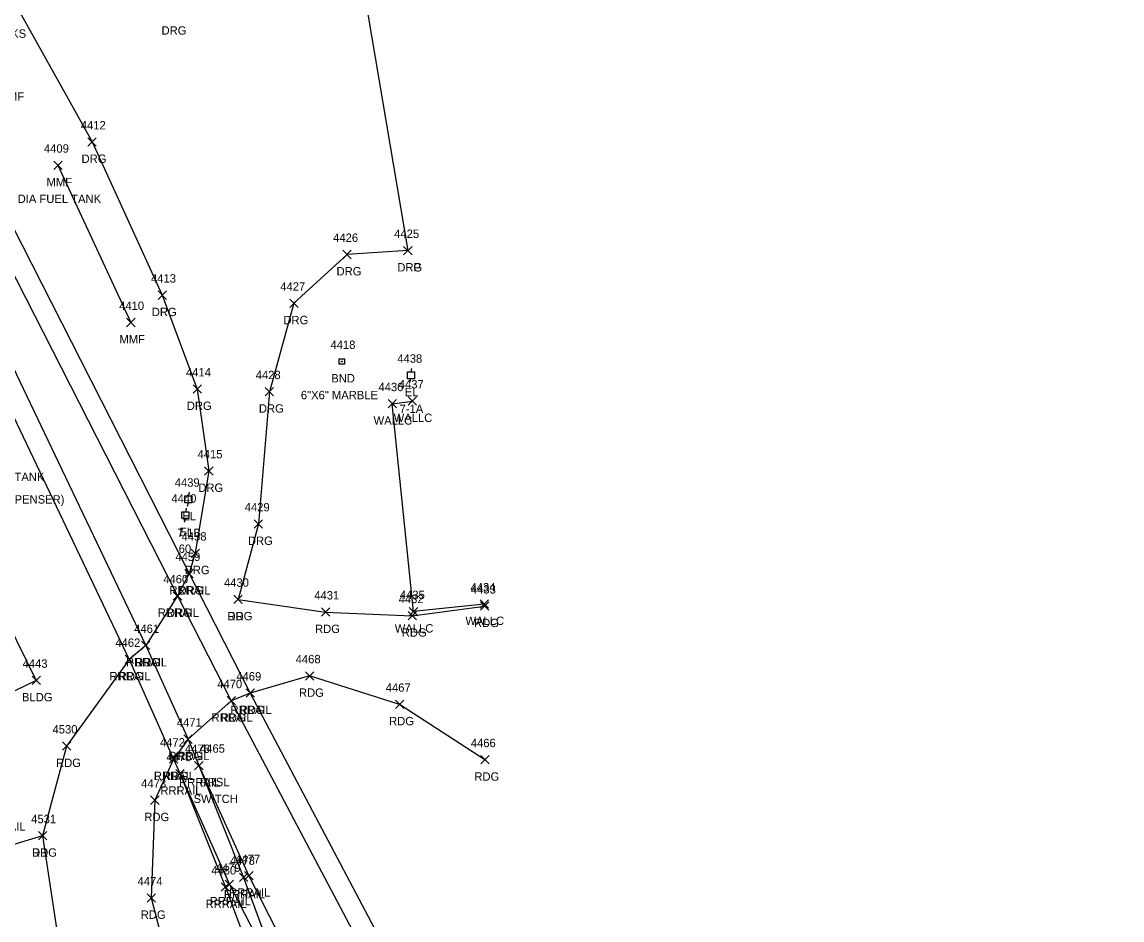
# Model space of a CAD drawing. Extents: x 1462668 to 1465147, y 550359 to 557351.
# Drawn here: x 1463947.5 to 1464209.9, y 555056.5 to 555270.7 of the extents above; entities that cross this region are included whole.
import ezdxf

# ---------------------------------------------------------------- set-up
doc = ezdxf.new("R2010")
doc.units = 0
for name, color, linetype in [('L_A', 7, 'Continuous'), ('L_C', 7, 'Continuous'), ('L_I', 7, 'Continuous'), ('L_TIC', 7, 'Continuous'), ('LBC', 7, 'Continuous'), ('LDEFAULT', 7, 'Continuous'), ('Level 18', 7, 'Continuous'), ('LW', 7, 'Continuous'), ('M_A', 7, 'Continuous'), ('M_C', 7, 'Continuous'), ('M_I', 7, 'Continuous'), ('P_A', 7, 'Continuous'), ('P_I', 7, 'Continuous'), ('P_TIC', 7, 'Continuous'), ('PEU', 7, 'Continuous'), ('R_A', 7, 'Continuous'), ('R_C', 7, 'Continuous'), ('R_I', 7, 'Continuous'), ('R_TIC', 7, 'Continuous'), ('RDG', 7, 'Continuous'), ('RDP', 7, 'Continuous'), ('RR', 7, 'Continuous'), ('U_A', 7, 'Continuous'), ('U_C', 7, 'Continuous'), ('U_I', 7, 'Continuous'), ('UEPT', 7, 'Continuous')]:
    doc.layers.add(name, color=color, linetype=linetype)

msp = doc.modelspace()

# ---------------------------------------------------------------- linework, layer by layer
at = {"layer": 'L_TIC'}
for points in [[(1463955.08, 555235.52), (1463957.08, 555237.52)], [(1463957.08, 555235.52), (1463955.08, 555237.52)], [(1463972.47, 555198.01), (1463974.47, 555200.01)], [(1463974.47, 555198.01), (1463972.47, 555200.01)], [(1464034.86, 555178.64), (1464036.86, 555180.64)], [(1464036.86, 555178.64), (1464034.86, 555180.64)], [(1464039.65, 555179.29), (1464041.65, 555181.29)], [(1464041.65, 555179.29), (1464039.65, 555181.29)], [(1464056.78, 555130.87), (1464058.78, 555132.87)], [(1464058.78, 555130.87), (1464056.78, 555132.87)], [(1464039.91, 555129.06), (1464041.91, 555131.06)], [(1464041.91, 555129.06), (1464039.91, 555131.06)], [(1463949.91, 555112.66), (1463951.91, 555114.66)], [(1463951.91, 555112.66), (1463949.91, 555114.66)]]:
    msp.add_lwpolyline(points, dxfattribs=at)
at = {"layer": 'LBC'}
msp.add_lwpolyline([(1463936.65, 555142.43), (1463950.91, 555113.66), (1463943.32, 555109.94), (1463929.12, 555138.49)], dxfattribs=at)
at = {"layer": 'LDEFAULT'}
msp.add_lwpolyline([(1463956.08, 555236.52), (1463973.47, 555199.01)], dxfattribs=at)
at = {"layer": 'Level 18'}
msp.add_lwpolyline([(1464023.17, 555190.33), (1464024.42, 555190.33), (1464024.42, 555189.08), (1464023.17, 555189.08)], close=True, dxfattribs=at)
msp.add_circle((1464023.8, 555189.71), 0.0833, dxfattribs=at)
at = {"layer": 'LW'}
msp.add_lwpolyline([(1464057.78, 555131.87), (1464040.91, 555130.06), (1464035.86, 555179.64), (1464040.65, 555180.29)], dxfattribs=at)
at = {"layer": 'P_TIC'}
for points in [[(1463998.05, 555131.98), (1464000.05, 555133.98)], [(1464000.05, 555131.98), (1463998.05, 555133.98)], [(1464018.93, 555128.95), (1464020.93, 555130.95)], [(1464020.93, 555128.95), (1464018.93, 555130.95)], [(1464039.63, 555128.08), (1464041.63, 555130.08)], [(1464041.63, 555128.08), (1464039.63, 555130.08)], [(1464056.86, 555130.37), (1464058.86, 555132.37)], [(1464058.86, 555130.37), (1464056.86, 555132.37)], [(1463976.02, 555120.98), (1463978.02, 555122.98)], [(1463978.02, 555120.98), (1463976.02, 555122.98)], [(1463972.09, 555117.65), (1463974.09, 555119.65)], [(1463974.09, 555117.65), (1463972.09, 555119.65)], [(1464015.11, 555113.73), (1464017.11, 555115.73)], [(1464017.11, 555113.73), (1464015.11, 555115.73)], [(1464000.96, 555109.62), (1464002.96, 555111.62)], [(1464002.96, 555109.62), (1464000.96, 555111.62)], [(1463996.43, 555107.79), (1463998.43, 555109.79)], [(1463998.43, 555107.79), (1463996.43, 555109.79)], [(1464036.6, 555106.94), (1464038.6, 555108.94)], [(1464038.6, 555106.94), (1464036.6, 555108.94)], [(1463957.14, 555096.99), (1463959.14, 555098.99)], [(1463959.14, 555096.99), (1463957.14, 555098.99)], [(1463986.14, 555098.63), (1463988.14, 555100.63)], [(1463988.14, 555098.63), (1463986.14, 555100.63)], [(1463982.69, 555093.87), (1463984.69, 555095.87)], [(1463984.69, 555093.87), (1463982.69, 555095.87)], [(1464056.94, 555093.72), (1464058.94, 555095.72)], [(1464058.94, 555093.72), (1464056.94, 555095.72)], [(1463978.2, 555084.08), (1463980.2, 555086.08)], [(1463980.2, 555084.08), (1463978.2, 555086.08)], [(1463951.41, 555075.59), (1463953.41, 555077.59)], [(1463953.41, 555075.59), (1463951.41, 555077.59)], [(1463977.35, 555060.77), (1463979.35, 555062.77)], [(1463979.35, 555060.77), (1463977.35, 555062.77)]]:
    msp.add_lwpolyline(points, dxfattribs=at)
at = {"layer": 'PEU'}
for points in [[(1463999.05, 555132.98), (1464019.93, 555129.95), (1464040.63, 555129.08), (1464057.86, 555131.37)], [(1463977.02, 555121.98), (1463973.09, 555118.65), (1463958.14, 555097.99), (1463952.41, 555076.59), (1463958.37, 555037.25), (1463974.3, 554985.88), (1463991.77, 554931.62), (1464003.96, 554890.94), (1464011.44, 554869.69), (1464014.63, 554855.08), (1464021.09, 554834.4), (1464036.69, 554798.98), (1464052.01, 554759.21), (1464073.2, 554710.63), (1464082.37, 554701.78), (1464089.9, 554691.06)], [(1464057.94, 555094.72), (1464037.6, 555107.94), (1464016.11, 555114.73), (1464001.96, 555110.62), (1463997.43, 555108.79), (1463987.14, 555099.63), (1463983.69, 555094.87), (1463979.2, 555085.08), (1463978.35, 555061.77), (1463988.09, 555023.99)]]:
    msp.add_lwpolyline(points, dxfattribs=at)
at = {"layer": 'R_TIC'}
for points in [[(1463963.23, 555241.07), (1463965.23, 555243.07)], [(1463965.23, 555241.07), (1463963.23, 555243.07)], [(1464038.56, 555215.18), (1464040.56, 555217.18)], [(1464040.56, 555215.18), (1464038.56, 555217.18)], [(1464038.56, 555215.18), (1464040.56, 555217.18)], [(1464040.56, 555215.18), (1464038.56, 555217.18)], [(1464024.06, 555214.24), (1464026.06, 555216.24)], [(1464026.06, 555214.24), (1464024.06, 555216.24)], [(1463979.98, 555204.53), (1463981.98, 555206.53)], [(1463981.98, 555204.53), (1463979.98, 555206.53)], [(1464011.38, 555202.6), (1464013.38, 555204.6)], [(1464013.38, 555202.6), (1464011.38, 555204.6)], [(1463988.33, 555182.15), (1463990.33, 555184.15)], [(1463990.33, 555182.15), (1463988.33, 555184.15)], [(1464005.53, 555181.51), (1464007.53, 555183.51)], [(1464007.53, 555181.51), (1464005.53, 555183.51)], [(1463991.08, 555162.61), (1463993.08, 555164.61)], [(1463993.08, 555162.61), (1463991.08, 555164.61)], [(1464002.92, 555149.96), (1464004.92, 555151.96)], [(1464004.92, 555149.96), (1464002.92, 555151.96)], [(1463987.84, 555142.99), (1463989.84, 555144.99)], [(1463989.84, 555142.99), (1463987.84, 555144.99)], [(1463986.38, 555138.13), (1463988.38, 555140.13)], [(1463988.38, 555138.13), (1463986.38, 555140.13)], [(1463986.38, 555138.13), (1463988.38, 555140.13)], [(1463988.38, 555138.13), (1463986.38, 555140.13)], [(1463983.61, 555132.81), (1463985.61, 555134.81)], [(1463985.61, 555132.81), (1463983.61, 555134.81)], [(1463983.61, 555132.81), (1463985.61, 555134.81)], [(1463985.61, 555132.81), (1463983.61, 555134.81)], [(1463998.05, 555131.98), (1464000.05, 555133.98)], [(1464000.05, 555131.98), (1463998.05, 555133.98)], [(1463976.02, 555120.98), (1463978.02, 555122.98)], [(1463978.02, 555120.98), (1463976.02, 555122.98)], [(1463976.02, 555120.98), (1463978.02, 555122.98)], [(1463978.02, 555120.98), (1463976.02, 555122.98)], [(1463972.09, 555117.65), (1463974.09, 555119.65)], [(1463974.09, 555117.65), (1463972.09, 555119.65)], [(1464000.96, 555109.62), (1464002.96, 555111.62)], [(1464002.96, 555109.62), (1464000.96, 555111.62)], [(1463996.43, 555107.79), (1463998.43, 555109.79)], [(1463998.43, 555107.79), (1463996.43, 555109.79)], [(1463986.14, 555098.63), (1463988.14, 555100.63)], [(1463988.14, 555098.63), (1463986.14, 555100.63)], [(1463982.69, 555093.87), (1463984.69, 555095.87)], [(1463984.69, 555093.87), (1463982.69, 555095.87)], [(1463988.7, 555092.34), (1463990.7, 555094.34)], [(1463990.7, 555092.34), (1463988.7, 555094.34)], [(1463988.7, 555092.34), (1463990.7, 555094.34)], [(1463990.7, 555092.34), (1463988.7, 555094.34)], [(1463984.23, 555090.39), (1463986.23, 555092.39)], [(1463986.23, 555090.39), (1463984.23, 555092.39)], [(1463984.23, 555090.39), (1463986.23, 555092.39)], [(1463986.23, 555090.39), (1463984.23, 555092.39)], [(1463951.41, 555075.59), (1463953.41, 555077.59)], [(1463953.41, 555075.59), (1463951.41, 555077.59)], [(1463999.39, 555065.67), (1464001.39, 555067.67)], [(1464001.39, 555065.67), (1463999.39, 555067.67)], [(1464000.63, 555066.05), (1464002.63, 555068.05)], [(1464002.63, 555066.05), (1464000.63, 555068.05)], [(1463995.02, 555063.35), (1463997.02, 555065.35)], [(1463997.02, 555063.35), (1463995.02, 555065.35)], [(1463996, 555064), (1463998, 555066)], [(1463998, 555064), (1463996, 555066)]]:
    msp.add_lwpolyline(points, dxfattribs=at)
at = {"layer": 'RDG'}
for points in [[(1463767.62, 555582.4), (1463756, 555576.04), (1463782.39, 555530.05), (1463811.87, 555483.03), (1463842.18, 555423.16), (1463871.29, 555375.01), (1463902.25, 555330.66), (1463943.27, 555279.83), (1463964.23, 555242.07), (1463980.98, 555205.53), (1463989.33, 555183.15), (1463992.08, 555163.61), (1463988.84, 555143.99), (1463987.38, 555139.13), (1463984.61, 555133.81), (1463977.02, 555121.98)], [(1464039.56, 555216.18), (1464025.06, 555215.24), (1464012.38, 555203.6), (1464006.53, 555182.51), (1464003.92, 555150.96), (1463999.05, 555132.98)], [(1463952.41, 555076.59), (1463933.98, 555071.02), (1463919.59, 555078.27), (1463901.44, 555117.76), (1463887.25, 555155.23), (1463873.79, 555184.26), (1463863.04, 555181.69)]]:
    msp.add_lwpolyline(points, dxfattribs=at)
at = {"layer": 'RDP'}
msp.add_lwpolyline([(1464023.21, 555313.06), (1464039.56, 555216.18)], dxfattribs=at)
at = {"layer": 'RR'}
for points in [[(1463738.3, 555592.1), (1463756.39, 555555.83), (1463773.18, 555522.79), (1463783.39, 555502.23), (1463795.59, 555478.87), (1463816.57, 555437.48), (1463830.94, 555409.51), (1463848.79, 555374.55), (1463899.55, 555272.92), (1463973.09, 555118.65), (1463983.69, 555094.87), (1463985.23, 555091.39), (1463997, 555065), (1464011.61, 555036.65), (1464026.5, 555008.18), (1464046.45, 554964.72), (1464065.66, 554916.67), (1464082.8, 554871.21), (1464093.87, 554842.43), (1464100.4, 554825.05), (1464129.92, 554747.44), (1464153.38, 554685.33), (1464180.48, 554613.64)], [(1463742.84, 555594.32), (1463760.75, 555558.08), (1463777.72, 555524.42), (1463787.9, 555504.12), (1463799.93, 555481.15), (1463819.96, 555441.9), (1463835.07, 555412.08), (1463853.2, 555376.47), (1463903.47, 555275.99), (1463977.02, 555121.98), (1463987.14, 555099.63), (1463989.7, 555093.34), (1464001.63, 555067.05), (1464016.17, 555038.45), (1464031.3, 555009.85), (1464051, 554966.45), (1464070.2, 554918.71), (1464087.5, 554872.76), (1464098.32, 554844.67), (1464105, 554826.89), (1464134.6, 554748.85), (1464158.08, 554686.95), (1464184.75, 554615.39)], [(1463799.93, 555481.15), (1463821.59, 555442.67), (1463839.41, 555414.19), (1463860.65, 555380.51), (1463909.95, 555291.33), (1463987.38, 555139.13), (1464001.96, 555110.62), (1464033.86, 555050.25), (1464055.66, 555009.67), (1464073.58, 554976.54), (1464098.59, 554931.9), (1464124.97, 554884.13), (1464136.72, 554860.51), (1464143.75, 554841.03), (1464169.78, 554757.06), (1464181.89, 554716.52), (1464214.17, 554610.47)], [(1463795.59, 555478.87), (1463818.35, 555438.44), (1463835.07, 555412.08), (1463856.18, 555378.13), (1463905.6, 555288.89), (1463984.61, 555133.81), (1463997.43, 555108.79), (1464030.1, 555046.89), (1464051.29, 555007.39), (1464069.23, 554974.41), (1464094.51, 554929.11), (1464121.14, 554880.83), (1464131.94, 554858.78), (1464139.09, 554839.52), (1464165.13, 554755.41), (1464177.59, 554713.72), (1464209.39, 554609.15)], [(1463989.7, 555093.34), (1464000.39, 555066.67), (1464022.62, 555006.41), (1464038.48, 554961.39), (1464055.17, 554912.23), (1464070.15, 554864.86), (1464079, 554837.21), (1464085.94, 554816.06), (1464092.4, 554795.76), (1464104.92, 554760.13), (1464114.82, 554731.8), (1464136.23, 554672.67), (1464181.12, 554559.09)], [(1463985.23, 555091.39), (1463996.02, 555064.35), (1464007.14, 555034.52), (1464018.03, 555004.65), (1464033.98, 554959.37), (1464050.76, 554909.64), (1464065.33, 554863.33), (1464074.3, 554835.57), (1464081.74, 554812.78), (1464087.8, 554794.52), (1464102.09, 554753.11), (1464110.14, 554729.95), (1464132.08, 554670.21), (1464176.36, 554557.09)]]:
    msp.add_lwpolyline(points, dxfattribs=at)
at = {"layer": 'UEPT'}
for p, q in [((1464040.46, 555188.08), (1464040.3, 555187.25)), ((1464039.46, 555185.58), (1464039.46, 555187.25)), ((1464039.46, 555187.25), (1464041.13, 555187.25)), ((1464041.13, 555185.58), (1464039.46, 555185.58)), ((1464040.05, 555184.75), (1464040.3, 555185.58)), ((1464040.3, 555186.42), (1464040.3, 555186.42)), ((1464041.13, 555187.25), (1464041.13, 555185.58)), ((1463986.38, 555156.02), (1463986.38, 555157.68)), ((1463986.38, 555157.68), (1463988.05, 555157.68)), ((1463987.38, 555158.52), (1463987.21, 555157.68)), ((1463987.21, 555156.85), (1463987.21, 555156.85)), ((1463988.05, 555157.68), (1463988.05, 555156.02)), ((1463985.67, 555152.23), (1463985.67, 555153.89)), ((1463985.67, 555153.89), (1463987.34, 555153.89)), ((1463988.05, 555156.02), (1463986.38, 555156.02)), ((1463986.67, 555154.73), (1463986.5, 555153.89)), ((1463986.96, 555155.18), (1463987.21, 555156.02)), ((1463987.34, 555153.89), (1463987.34, 555152.23)), ((1463987.34, 555152.23), (1463985.67, 555152.23)), ((1463986.25, 555151.39), (1463986.5, 555152.23)), ((1463986.5, 555153.06), (1463986.5, 555153.06))]:
    msp.add_line(p, q, dxfattribs=at)

# ---------------------------------------------------------------- texts
at = {"layer": 'L_A'}
for s, p in [('MMF', (1463941.92, 555251.92)), ('MMF', (1463953.37, 555231.52)), ('MMF', (1463970.75, 555194.01)), ('WALLC', (1464036.18, 555175.29)), ('WALLC', (1464031.39, 555174.64)), ('WALLC', (1464053.31, 555126.87)), ('WALLC', (1464036.44, 555125.06)), ('BLDG', (1463947.5, 555108.66))]:
    msp.add_text(s, height=2, dxfattribs=at).set_placement(p)
at = {"layer": 'L_C'}
for s, p in [("10.0' DIA FUEL TANKS", (1463920.34, 555266.93)), ("8.0' DIA FUEL TANK", (1463941.5, 555227.52)), ('LIQUID CALCIUM CHLORIDE  TANK', (1463907.98, 555161.2)), ('METAL CONEX (DISPENSER)', (1463920.48, 555155.82))]:
    msp.add_text(s, height=2, dxfattribs=at).set_placement(p)
at = {"layer": 'L_I'}
for s, p in [('4409', (1463952.74, 555239.52)), ('4410', (1463970.69, 555202.01)), ('4437', (1464037.39, 555183.29)), ('4436', (1464032.54, 555182.64)), ('4434', (1464054.52, 555134.87)), ('4435', (1464037.65, 555133.06)), ('4443', (1463947.65, 555116.66))]:
    msp.add_text(s, height=2, dxfattribs=at).set_placement(p)
at = {"layer": 'M_A'}
msp.add_text('BND', height=2, dxfattribs=at).set_placement((1464021.29, 555184.71))
at = {"layer": 'M_C'}
msp.add_text('6"X6" MARBLE', height=2, dxfattribs=at).set_placement((1464014.04, 555180.71))
at = {"layer": 'M_I'}
msp.add_text('4418', height=2, dxfattribs=at).set_placement((1464021.11, 555192.71))
at = {"layer": 'P_A'}
for p in [(1463996.53, 555127.98), (1464055.35, 555126.37), (1464017.42, 555124.95), (1464038.12, 555124.08), (1463974.51, 555116.98), (1463970.58, 555113.65), (1464013.59, 555109.73), (1463999.44, 555105.62), (1463994.92, 555103.79), (1464035.09, 555102.94), (1463984.63, 555094.63), (1463955.63, 555092.99), (1463981.18, 555089.87), (1464055.43, 555089.72), (1463976.69, 555080.08), (1463949.9, 555071.59), (1463975.84, 555056.77)]:
    msp.add_text('RDG', height=2, dxfattribs=at).set_placement(p)
at = {"layer": 'P_I'}
for s, p in [('4430', (1463995.7, 555135.98)), ('4433', (1464054.6, 555134.37)), ('4431', (1464017.24, 555132.95)), ('4432', (1464037.37, 555132.08)), ('4461', (1463974.28, 555124.98)), ('4462', (1463969.78, 555121.65)), ('4468', (1464012.8, 555117.73)), ('4469', (1463998.64, 555113.62)), ('4470', (1463994.09, 555111.79)), ('4467', (1464034.29, 555110.94)), ('4471', (1463984.45, 555102.63)), ('4530', (1463954.79, 555100.99)), ('4472', (1463980.43, 555097.87)), ('4466', (1464054.58, 555097.72)), ('4473', (1463975.94, 555088.08)), ('4531', (1463949.71, 555079.59)), ('4474', (1463975.09, 555064.77))]:
    msp.add_text(s, height=2, dxfattribs=at).set_placement(p)
at = {"layer": 'R_A'}
for s, p in [('DRG', (1463980.8, 555267.67)), ('DRG', (1463961.72, 555237.07)), ('DRG', (1464022.55, 555210.24)), ('DRG', (1464037.05, 555211.18)), ('DRP', (1464037.05, 555211.18)), ('DRG', (1463978.47, 555200.53)), ('DRG', (1464009.87, 555198.6)), ('DRG', (1463986.82, 555178.15)), ('DRG', (1464004.02, 555177.51)), ('DRG', (1463989.57, 555158.61)), ('DRG', (1464001.41, 555145.96)), ('DRG', (1463986.33, 555138.99)), ('RRRAIL', (1463982.67, 555134.13)), ('DRG', (1463984.86, 555134.13)), ('RRRAIL', (1463979.9, 555128.81)), ('DRG', (1463982.1, 555128.81)), ('DRG', (1463996.53, 555127.98)), ('RRRAIL', (1463972.32, 555116.98)), ('DRG', (1463974.51, 555116.98)), ('RRRAIL', (1463968.38, 555113.65)), ('RRRAIL', (1463997.25, 555105.62)), ('RRRAIL', (1463992.72, 555103.79)), ('RRRAIL', (1463982.44, 555094.63)), ('RRRAIL', (1463978.98, 555089.87)), ('RRRAIL', (1463980.52, 555086.39)), ('RRRAIL', (1463980.52, 555086.39)), ('RRRAIL', (1463984.99, 555088.34)), ('RRRAIL', (1463984.99, 555088.34)), ('RRSL', (1463989.89, 555088.4)), ('RRRAIL', (1463938.54, 555077.83)), ('DRG', (1463949.9, 555071.59)), ('RRRAIL', (1463992.29, 555060)), ('RRRAIL', (1463995.68, 555061.67)), ('RRRAIL', (1463996.93, 555062.05)), ('RRRAIL', (1463991.31, 555059.35))]:
    msp.add_text(s, height=2, dxfattribs=at).set_placement(p)
at = {"layer": 'R_C'}
msp.add_text('SWITCH', height=2, dxfattribs=at).set_placement((1463988.45, 555084.4))
at = {"layer": 'R_I'}
for s, p in [('4412', (1463961.54, 555245.07)), ('4426', (1464021.74, 555218.24)), ('4425', (1464036.3, 555219.18)), ('4425', (1464036.3, 555219.18)), ('4413', (1463978.29, 555208.53)), ('4427', (1464009.12, 555206.6)), ('4414', (1463986.63, 555186.15)), ('4428', (1464003.27, 555185.51)), ('4415', (1463989.39, 555166.61)), ('4429', (1464000.65, 555153.96)), ('4458', (1463985.58, 555146.99)), ('4459', (1463984.11, 555142.13)), ('4459', (1463984.11, 555142.13)), ('4460', (1463981.22, 555136.81)), ('4460', (1463981.22, 555136.81)), ('4430', (1463995.7, 555135.98)), ('4461', (1463974.28, 555124.98)), ('4461', (1463974.28, 555124.98)), ('4462', (1463969.78, 555121.65)), ('4469', (1463998.64, 555113.62)), ('4470', (1463994.09, 555111.79)), ('4471', (1463984.45, 555102.63)), ('4472', (1463980.43, 555097.87)), ('4475', (1463981.97, 555094.39)), ('4475', (1463981.97, 555094.39)), ('4476', (1463986.38, 555096.34)), ('4476', (1463986.38, 555096.34)), ('4465', (1463989.98, 555096.4)), ('4531', (1463949.71, 555079.59)), ('4479', (1463993.73, 555068)), ('4478', (1463997.13, 555069.67)), ('4477', (1463998.37, 555070.05)), ('4480', (1463992.67, 555067.35))]:
    msp.add_text(s, height=2, dxfattribs=at).set_placement(p)
at = {"layer": 'U_A'}
for p in [(1464038.83, 555181.42), (1463985.75, 555151.85), (1463985.04, 555148.06)]:
    msp.add_text('EL', height=2, dxfattribs=at).set_placement(p)
at = {"layer": 'U_C'}
for s, p in [('7-1A', (1464037.59, 555177.42)), ('7-1B', (1463984.55, 555147.85)), ('60', (1463984.9, 555144.06))]:
    msp.add_text(s, height=2, dxfattribs=at).set_placement(p)
at = {"layer": 'U_I'}
for s, p in [('4438', (1464037.04, 555189.42)), ('4439', (1463983.95, 555159.85)), ('4440', (1463983.16, 555156.06))]:
    msp.add_text(s, height=2, dxfattribs=at).set_placement(p)

doc.saveas('drawing.dxf')
